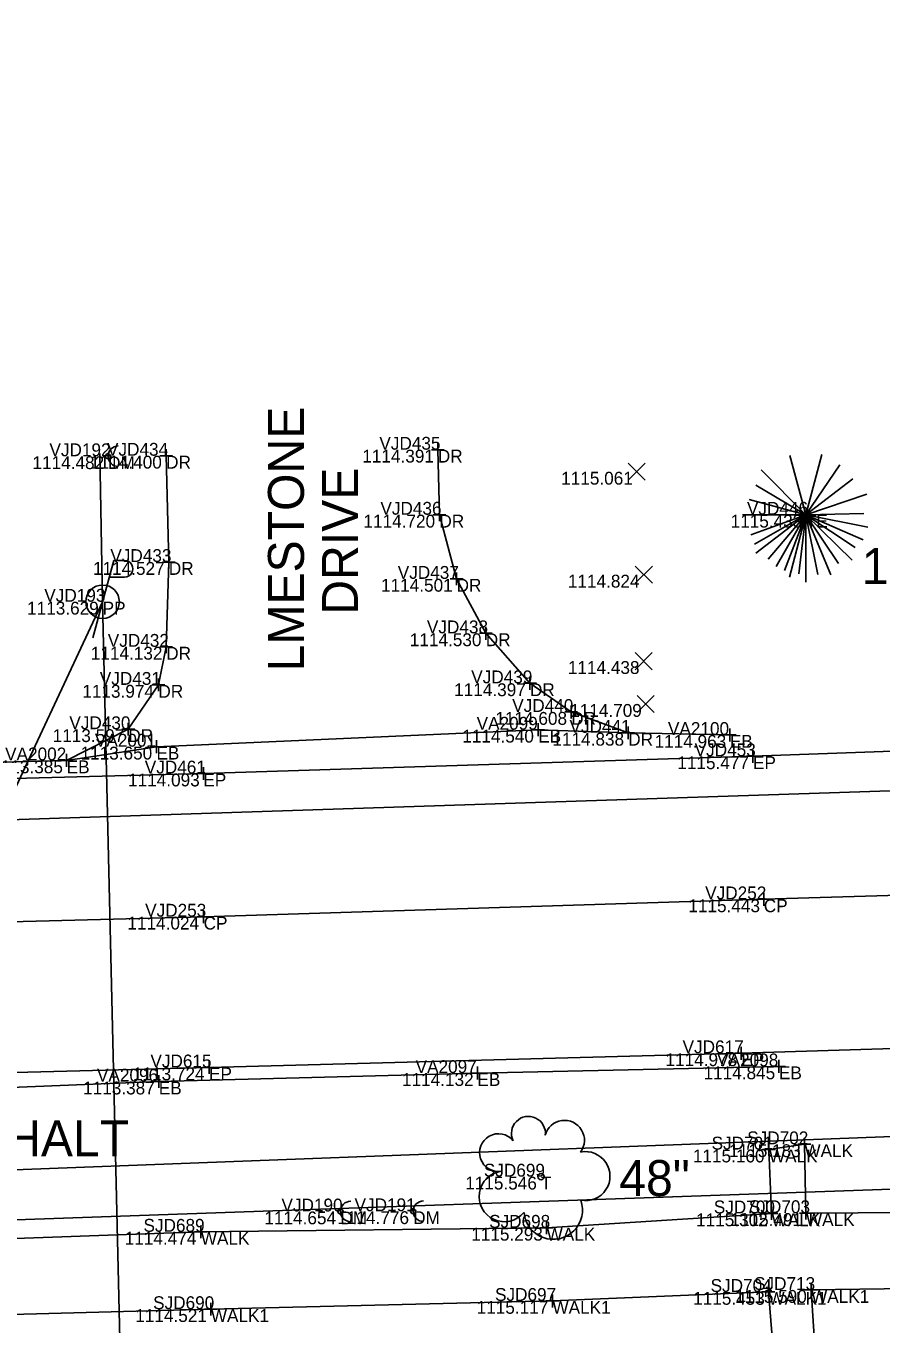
# Model space of a CAD drawing. Extents: x 1629915 to 1630675, y 484401 to 484601.
# Drawn here: x 1630554.5 to 1630621.1, y 484466.8 to 484567.8 of the extents above; entities that cross this region are included whole.
import ezdxf

# ---------------------------------------------------------------- set-up
doc = ezdxf.new("R2010")
doc.units = 0
for name, color, linetype in [('BR_X_Sub_Foot_Object', 7, 'Continuous'), ('PV_X_COP', 7, 'Continuous'), ('PV_X_Driveway', 7, 'Continuous'), ('PV_X_EOP', 7, 'Continuous'), ('PV_X_Shoulder_Aggregate', 7, 'Continuous'), ('PV_X_Walk', 7, 'Continuous'), ('SV_X_Random_Point', 7, 'Continuous'), ('SV_X_Shot_Marker', 7, 'Continuous'), ('SV_X_Text_Comment', 7, 'Continuous'), ('SV_X_Text_Elevation', 7, 'Continuous'), ('SV_X_Text_Name', 7, 'Continuous'), ('TX_X_20', 7, 'Continuous'), ('UT_X_Electric_Cells', 7, 'Continuous'), ('UT_X_Misc_Cells', 7, 'Continuous'), ('UT_X_Sanitary_Line', 7, 'Continuous'), ('UT_X_Water', 7, 'Continuous'), ('VG_X_Cells', 7, 'Continuous')]:
    doc.layers.add(name, color=color, linetype=linetype)

msp = doc.modelspace()

# ---------------------------------------------------------------- linework, layer by layer
at = {"layer": 'BR_X_Sub_Foot_Object'}
for p, q in [((1630560.47, 484522.99), (1630560.26, 484534.52)), ((1630537.67, 484474.32), (1630560.47, 484522.99)), ((1630562.17, 484449.9), (1630560.47, 484522.99)), ((1630537.67, 484474.32), (1630673.62, 484479.09))]:
    msp.add_line(p, q, dxfattribs=at)
at = {"layer": 'PV_X_COP'}
msp.add_lwpolyline([(1630297.37, 484489.97), (1630308.55, 484490.49), (1630361.84, 484492.4), (1630403.57, 484493.66), (1630440.46, 484494.93), (1630486.15, 484496.21), (1630529.23, 484497.46), (1630568.33, 484498.48), (1630611.93, 484499.83), (1630649.71, 484500.97)], dxfattribs=at)
at = {"layer": 'PV_X_Driveway'}
for points in [[(1630557.67, 484510.64), (1630562.47, 484513.07), (1630564.81, 484516.52), (1630565.42, 484519.48), (1630565.62, 484526.08), (1630565.41, 484534.35)], [(1630586.56, 484534.82), (1630586.68, 484529.76), (1630588.02, 484524.77), (1630590.29, 484520.53), (1630593.73, 484516.64), (1630596.94, 484514.41), (1630601.38, 484512.79)]]:
    msp.add_lwpolyline(points, dxfattribs=at)
at = {"layer": 'PV_X_EOP'}
for points in [[(1630649.54, 484512.34), (1630611.09, 484510.96), (1630568.31, 484509.62), (1630527.92, 484508.55), (1630486.05, 484507.69), (1630439.97, 484506.41), (1630403.1, 484505.48), (1630361.88, 484504.43), (1630301.74, 484502.19)], [(1630292.71, 484478.56), (1630303.89, 484478.68), (1630360.91, 484480.85), (1630403.55, 484482.24), (1630442.06, 484483.47), (1630486.34, 484484.8), (1630529.42, 484485.73), (1630568.75, 484486.75), (1630610.18, 484487.85), (1630650.03, 484489.09)]]:
    msp.add_lwpolyline(points, dxfattribs=at)
at = {"layer": 'PV_X_Shoulder_Aggregate'}
for points in [[(1630609.29, 484512.62), (1630601.38, 484512.79), (1630594.37, 484513.03), (1630564.66, 484511.71), (1630557.67, 484510.64), (1630535.06, 484510.05), (1630513.96, 484509.73), (1630489.96, 484510.39), (1630468.46, 484511.02), (1630445.09, 484511.2), (1630420.71, 484511.45), (1630393.49, 484511.94), (1630369.15, 484512.29), (1630344.7, 484511.85), (1630320.66, 484510.61), (1630304.12, 484509.44), (1630303.96, 484508.98)], [(1630290.02, 484472.09), (1630316.06, 484472.69), (1630342.81, 484473.66), (1630368.02, 484474.92), (1630386.58, 484475.76), (1630401.76, 484475.86), (1630425.59, 484476.97), (1630451.8, 484477.68), (1630475.37, 484478.48), (1630505.19, 484479.36), (1630508.15, 484481.33), (1630508.06, 484484.39), (1630516.81, 484484.74), (1630516.95, 484481.1), (1630520.69, 484479.6), (1630540.99, 484479.18), (1630540.51, 484484.67), (1630564.84, 484485.65), (1630589.64, 484486.31), (1630613.11, 484486.83)]]:
    msp.add_lwpolyline(points, dxfattribs=at)
at = {"layer": 'PV_X_Walk'}
for p, q in [((1630615.09, 484480.77), (1630612.33, 484480.36)), ((1630615.21, 484475.41), (1630615.09, 484480.77)), ((1630612.33, 484480.36), (1630612.53, 484475.39)), ((1630612.53, 484475.39), (1630595.02, 484474.27)), ((1630631.16, 484475.53), (1630615.21, 484475.41)), ((1630568.11, 484473.96), (1630535.86, 484472.8)), ((1630595.02, 484474.27), (1630568.11, 484473.96))]:
    msp.add_line(p, q, dxfattribs=at)
msp.add_lwpolyline([(1630493.48, 484465.78), (1630510.56, 484466.34), (1630535.88, 484467.05), (1630568.89, 484467.94), (1630595.48, 484468.58), (1630612.29, 484469.28), (1630612.76, 484463.55), (1630612.78, 484463.44), (1630611.46, 484463.36), (1630611.74, 484459.19), (1630617.57, 484459.66), (1630617.01, 484463.77), (1630616.02, 484463.69), (1630615.97, 484463.78), (1630615.61, 484469.43), (1630634.53, 484469.7), (1630634.52, 484474.41), (1630639.35, 484473.67), (1630639.45, 484470.09), (1630649.39, 484470.38)], dxfattribs=at)
at = {"layer": 'SV_X_Random_Point'}
for p, q in [((1630601.37, 484532.44), (1630602.71, 484533.77)), ((1630601.37, 484533.77), (1630602.71, 484532.44)), ((1630601.93, 484524.43), (1630603.26, 484525.76)), ((1630601.93, 484525.76), (1630603.26, 484524.43)), ((1630601.92, 484517.7), (1630603.25, 484519.04)), ((1630601.92, 484519.04), (1630603.25, 484517.7)), ((1630602.07, 484514.36), (1630603.41, 484515.7)), ((1630602.07, 484515.7), (1630603.41, 484514.36))]:
    msp.add_line(p, q, dxfattribs=at)
at = {"layer": 'SV_X_Shot_Marker'}
for p, q in [((1630586.56, 484535.32), (1630586.56, 484534.32)), ((1630564.91, 484534.35), (1630565.91, 484534.35)), ((1630565.41, 484534.85), (1630565.41, 484533.85)), ((1630565.41, 484534.35), (1630565.41, 484534.35)), ((1630586.06, 484534.82), (1630587.06, 484534.82)), ((1630586.56, 484534.82), (1630586.56, 484534.82)), ((1630586.68, 484530.26), (1630586.68, 484529.26)), ((1630586.18, 484529.76), (1630587.18, 484529.76)), ((1630586.68, 484529.76), (1630586.68, 484529.76)), ((1630565.12, 484526.08), (1630566.12, 484526.08)), ((1630565.62, 484526.58), (1630565.62, 484525.58)), ((1630565.62, 484526.08), (1630565.62, 484526.08)), ((1630588.02, 484525.27), (1630588.02, 484524.27)), ((1630587.52, 484524.77), (1630588.52, 484524.77)), ((1630588.02, 484524.77), (1630588.02, 484524.77)), ((1630590.29, 484521.03), (1630590.29, 484520.03)), ((1630565.42, 484519.98), (1630565.42, 484518.98)), ((1630589.79, 484520.53), (1630590.79, 484520.53)), ((1630590.29, 484520.53), (1630590.29, 484520.53)), ((1630564.92, 484519.48), (1630565.92, 484519.48)), ((1630565.42, 484519.48), (1630565.42, 484519.48)), ((1630564.81, 484517.02), (1630564.81, 484516.02)), ((1630593.73, 484517.14), (1630593.73, 484516.14)), ((1630564.31, 484516.52), (1630565.31, 484516.52)), ((1630564.81, 484516.52), (1630564.81, 484516.52)), ((1630593.23, 484516.64), (1630594.23, 484516.64)), ((1630593.73, 484516.64), (1630593.73, 484516.64)), ((1630596.94, 484514.91), (1630596.94, 484513.91)), ((1630596.44, 484514.41), (1630597.44, 484514.41)), ((1630596.94, 484514.41), (1630596.94, 484514.41)), ((1630561.97, 484513.07), (1630562.97, 484513.07)), ((1630562.47, 484513.57), (1630562.47, 484512.57)), ((1630562.47, 484513.07), (1630562.47, 484513.07)), ((1630593.87, 484513.03), (1630594.87, 484513.03)), ((1630594.37, 484513.53), (1630594.37, 484512.53)), ((1630594.37, 484513.03), (1630594.37, 484513.03)), ((1630600.88, 484512.79), (1630601.88, 484512.79)), ((1630601.38, 484513.29), (1630601.38, 484512.29)), ((1630601.38, 484512.79), (1630601.38, 484512.79)), ((1630609.29, 484513.12), (1630609.29, 484512.12)), ((1630564.16, 484511.71), (1630565.16, 484511.71)), ((1630564.66, 484512.21), (1630564.66, 484511.21)), ((1630564.66, 484511.71), (1630564.66, 484511.71)), ((1630608.79, 484512.62), (1630609.79, 484512.62)), ((1630609.29, 484512.62), (1630609.29, 484512.62)), ((1630557.67, 484511.14), (1630557.67, 484510.14)), ((1630610.59, 484510.96), (1630611.59, 484510.96)), ((1630611.09, 484511.46), (1630611.09, 484510.46)), ((1630611.09, 484510.96), (1630611.09, 484510.96)), ((1630557.17, 484510.64), (1630558.17, 484510.64)), ((1630557.67, 484510.64), (1630557.67, 484510.64)), ((1630568.31, 484510.12), (1630568.31, 484509.12)), ((1630567.81, 484509.62), (1630568.81, 484509.62)), ((1630568.31, 484509.62), (1630568.31, 484509.62)), ((1630611.43, 484499.83), (1630612.43, 484499.83)), ((1630611.93, 484500.33), (1630611.93, 484499.33)), ((1630611.93, 484499.83), (1630611.93, 484499.83)), ((1630568.33, 484498.98), (1630568.33, 484497.98)), ((1630567.83, 484498.48), (1630568.83, 484498.48)), ((1630568.33, 484498.48), (1630568.33, 484498.48)), ((1630609.68, 484487.85), (1630610.68, 484487.85)), ((1630610.18, 484488.35), (1630610.18, 484487.35)), ((1630610.18, 484487.85), (1630610.18, 484487.85)), ((1630568.25, 484486.75), (1630569.25, 484486.75)), ((1630568.75, 484487.25), (1630568.75, 484486.25)), ((1630568.75, 484486.75), (1630568.75, 484486.75)), ((1630589.64, 484486.81), (1630589.64, 484485.81)), ((1630612.61, 484486.83), (1630613.61, 484486.83)), ((1630613.11, 484487.33), (1630613.11, 484486.33)), ((1630613.11, 484486.83), (1630613.11, 484486.83)), ((1630564.34, 484485.65), (1630565.34, 484485.65)), ((1630564.84, 484486.15), (1630564.84, 484485.15)), ((1630564.84, 484485.65), (1630564.84, 484485.65)), ((1630589.14, 484486.31), (1630590.14, 484486.31)), ((1630589.64, 484486.31), (1630589.64, 484486.31)), ((1630612.33, 484480.86), (1630612.33, 484479.86)), ((1630614.59, 484480.77), (1630615.59, 484480.77)), ((1630615.09, 484481.27), (1630615.09, 484480.27)), ((1630615.09, 484480.77), (1630615.09, 484480.77)), ((1630611.83, 484480.36), (1630612.83, 484480.36)), ((1630612.33, 484480.36), (1630612.33, 484480.36)), ((1630612.03, 484475.39), (1630613.03, 484475.39)), ((1630612.53, 484475.89), (1630612.53, 484474.89)), ((1630612.53, 484475.39), (1630612.53, 484475.39)), ((1630614.71, 484475.41), (1630615.71, 484475.41)), ((1630615.21, 484475.91), (1630615.21, 484474.91)), ((1630615.21, 484475.41), (1630615.21, 484475.41)), ((1630568.11, 484474.46), (1630568.11, 484473.46)), ((1630595.02, 484474.77), (1630595.02, 484473.77)), ((1630567.61, 484473.96), (1630568.61, 484473.96)), ((1630568.11, 484473.96), (1630568.11, 484473.96)), ((1630594.52, 484474.27), (1630595.52, 484474.27)), ((1630595.02, 484474.27), (1630595.02, 484474.27)), ((1630612.29, 484469.78), (1630612.29, 484468.78)), ((1630615.11, 484469.43), (1630616.11, 484469.43)), ((1630615.61, 484469.93), (1630615.61, 484468.93)), ((1630615.61, 484469.43), (1630615.61, 484469.43)), ((1630568.89, 484468.44), (1630568.89, 484467.44)), ((1630594.98, 484468.58), (1630595.98, 484468.58)), ((1630595.48, 484469.08), (1630595.48, 484468.08)), ((1630595.48, 484468.58), (1630595.48, 484468.58)), ((1630611.79, 484469.28), (1630612.79, 484469.28)), ((1630612.29, 484469.28), (1630612.29, 484469.28)), ((1630568.39, 484467.94), (1630569.39, 484467.94)), ((1630568.89, 484467.94), (1630568.89, 484467.94))]:
    msp.add_line(p, q, dxfattribs=at)
at = {"layer": 'UT_X_Electric_Cells'}
for p, q in [((1630561.33, 484526.19), (1630559.72, 484520.19)), ((1630561.33, 484526.19), (1630562.18, 484526.19)), ((1630560.99, 484524.91), (1630562.18, 484524.91))]:
    msp.add_line(p, q, dxfattribs=at)
msp.add_circle((1630560.47, 484522.99), 1.3, dxfattribs=at)
msp.add_arc((1630562.19, 484525.55), 0.638, 268.8767, 91.1233, dxfattribs=at)
at = {"layer": 'UT_X_Misc_Cells'}
for centre in [(1630560.89, 484534.31), (1630578.98, 484475.54), (1630584.64, 484475.56)]:
    msp.add_circle(centre, 0.2, dxfattribs=at)
for centre in [(1630561.69, 484534.31), (1630585.44, 484475.56), (1630579.78, 484475.54)]:
    msp.add_arc(centre, 0.8, 90, 270, dxfattribs=at)
at = {"layer": 'UT_X_Sanitary_Line'}
msp.add_lwpolyline([(1629930.75, 484483.73), (1630048.13, 484488.31), (1630252.72, 484494.6), (1630261.76, 484567.79), (1630373.42, 484500.09), (1630654.86, 484509.35)], dxfattribs=at)
at = {"layer": 'UT_X_Water'}
msp.add_line((1630348.22, 484470.93), (1630675.08, 484483.41), dxfattribs=at)
at = {"layer": 'VG_X_Cells'}
for p, q in [((1630615.21, 484529.76), (1630613.97, 484534.37)), ((1630615.21, 484529.76), (1630616.46, 484534.45)), ((1630615.21, 484529.76), (1630611.72, 484533.24)), ((1630615.21, 484529.76), (1630617.86, 484533.64)), ((1630615.21, 484529.76), (1630611.3, 484532.05)), ((1630615.21, 484529.76), (1630618.86, 484532.56)), ((1630615.21, 484529.76), (1630610.79, 484530.94)), ((1630615.21, 484529.76), (1630619.94, 484531.36)), ((1630610.27, 484529.76), (1630615.21, 484529.76)), ((1630615.21, 484529.76), (1630610.92, 484528.19)), ((1630615.21, 484529.76), (1630611.22, 484527.47)), ((1630615.21, 484529.76), (1630611.3, 484526.76)), ((1630615.21, 484529.76), (1630612.26, 484526.29)), ((1630615.21, 484529.76), (1630612.89, 484525.74)), ((1630615.21, 484529.76), (1630613.54, 484525.42)), ((1630615.21, 484529.76), (1630613.94, 484524.9)), ((1630615.21, 484529.76), (1630614.67, 484525.16)), ((1630615.21, 484529.76), (1630619.72, 484529.85)), ((1630615.21, 484524.52), (1630615.21, 484529.76)), ((1630615.21, 484529.76), (1630616.13, 484525.12)), ((1630615.21, 484529.76), (1630617.14, 484525.09)), ((1630615.21, 484529.76), (1630617.74, 484525.96)), ((1630615.21, 484529.76), (1630618.8, 484526.23)), ((1630615.21, 484529.76), (1630619.03, 484527.2)), ((1630615.21, 484529.76), (1630619.67, 484527.81)), ((1630615.21, 484529.76), (1630620.04, 484528.8))]:
    msp.add_line(p, q, dxfattribs=at)
msp.add_circle((1630594.59, 484478.25), 0.24, dxfattribs=at)
for centre, radius, start, end in [((1630593.61, 484481.62), 1.32, 354.0047, 205.9741), ((1630596.42, 484481.08), 1.55, 323.83, 165.0376), ((1630591.28, 484480.12), 1.47, 39.0625, 279.5412), ((1630598.05, 484478.29), 1.91, 259.1453, 101.4596), ((1630591.74, 484476.71), 1.97, 96.1722, 320.5737), ((1630595.54, 484475.65), 2.28, 184.9476, 19.4572)]:
    msp.add_arc(centre, radius, start, end, dxfattribs=at)

# ---------------------------------------------------------------- texts
at = {"layer": 'SV_X_Text_Comment'}
for s, p in [('DM', (1630560.89, 484533.31)), ('DR', (1630565.41, 484533.35)), ('DR', (1630586.56, 484533.82)), ('DR', (1630586.68, 484528.76)), ('TE', (1630615.21, 484528.76)), ('DR', (1630565.62, 484525.08)), ('DR', (1630588.02, 484523.77)), ('PP', (1630560.47, 484521.99)), ('DR', (1630590.29, 484519.53)), ('DR', (1630565.42, 484518.48)), ('DR', (1630564.81, 484515.52)), ('DR', (1630593.73, 484515.64)), ('DR', (1630596.94, 484513.41)), ('DR', (1630562.47, 484512.07)), ('EB', (1630594.37, 484512.03)), ('DR', (1630601.38, 484511.79)), ('EB', (1630564.66, 484510.71)), ('EB', (1630609.29, 484511.62)), ('EP', (1630611.09, 484509.96)), ('EB', (1630557.67, 484509.64)), ('EP', (1630568.31, 484508.62)), ('CP', (1630611.93, 484498.83)), ('CP', (1630568.33, 484497.48)), ('EP', (1630610.18, 484486.85)), ('EP', (1630568.75, 484485.75)), ('EB', (1630613.11, 484485.83)), ('EB', (1630564.84, 484484.65)), ('EB', (1630589.64, 484485.31)), ('WALK', (1630615.09, 484479.77)), ('WALK', (1630612.33, 484479.36)), ('T', (1630594.59, 484477.25)), ('DM', (1630578.98, 484474.54)), ('DM', (1630584.64, 484474.56)), ('WALK', (1630612.53, 484474.39)), ('WALK', (1630615.21, 484474.41)), ('WALK', (1630568.11, 484472.96)), ('WALK', (1630595.02, 484473.27)), ('WALK1', (1630615.61, 484468.43)), ('WALK1', (1630595.48, 484467.58)), ('WALK1', (1630612.29, 484468.28)), ('WALK1', (1630568.89, 484466.94))]:
    msp.add_text(s, height=1, dxfattribs=at).set_placement(p)
at = {"layer": 'SV_X_Text_Elevation'}
for s, p in [('1114.482', (1630555.01, 484533.31)), ('1114.400', (1630559.5, 484533.35)), ('1114.391', (1630580.68, 484533.82)), ('1115.061', (1630596.16, 484532.1)), ('1114.720', (1630580.77, 484528.76)), ('1115.433', (1630609.35, 484528.76)), ('1114.527', (1630559.72, 484525.08)), ('1114.824', (1630596.68, 484524.09)), ('1114.501', (1630582.14, 484523.77)), ('1113.629', (1630554.59, 484521.99)), ('1114.530', (1630584.38, 484519.53)), ('1114.132', (1630559.55, 484518.48)), ('1114.438', (1630596.68, 484517.37)), ('1113.974', (1630558.89, 484515.52)), ('1114.397', (1630587.83, 484515.64)), ('1114.709', (1630596.86, 484514.03)), ('1114.608', (1630591.04, 484513.41)), ('1113.597', (1630556.58, 484512.07)), ('1114.540', (1630588.46, 484512.03)), ('1114.838', (1630595.48, 484511.79)), ('1113.650', (1630558.75, 484510.71)), ('1114.963', (1630603.43, 484511.62)), ('1115.477', (1630605.2, 484509.96)), ('1113.385', (1630551.8, 484509.64)), ('1114.093', (1630562.45, 484508.62)), ('1115.443', (1630606.06, 484498.83)), ('1114.024', (1630562.4, 484497.48)), ('1114.978', (1630604.28, 484486.85)), ('1113.724', (1630562.83, 484485.75)), ('1114.845', (1630607.24, 484485.83)), ('1113.387', (1630558.95, 484484.65)), ('1114.132', (1630583.77, 484485.31)), ('1115.183', (1630609.23, 484479.77)), ('1115.160', (1630606.41, 484479.36)), ('1115.546', (1630588.69, 484477.25)), ('1114.654', (1630573.06, 484474.54)), ('1114.776', (1630578.74, 484474.56)), ('1115.302', (1630606.66, 484474.39)), ('1115.491', (1630609.33, 484474.41)), ('1114.474', (1630562.19, 484472.96)), ('1115.293', (1630589.16, 484473.27)), ('1115.453', (1630606.43, 484468.28)), ('1115.590', (1630609.7, 484468.43)), ('1115.117', (1630589.58, 484467.58)), ('1114.521', (1630563.01, 484466.94))]:
    msp.add_text(s, height=1, dxfattribs=at).set_placement(p)
at = {"layer": 'SV_X_Text_Name'}
for s, p in [('VJD192', (1630556.33, 484534.31)), ('VJD434', (1630560.81, 484534.35)), ('VJD435', (1630582.01, 484534.82)), ('VJD436', (1630582.09, 484529.76)), ('VJD446', (1630610.62, 484529.76)), ('VJD433', (1630561.07, 484526.08)), ('VJD437', (1630583.44, 484524.77)), ('VJD193', (1630555.93, 484522.99)), ('VJD438', (1630585.71, 484520.53)), ('VJD432', (1630560.87, 484519.48)), ('VJD431', (1630560.25, 484516.52)), ('VJD439', (1630589.16, 484516.64)), ('VJD440', (1630592.35, 484514.41)), ('VJD430', (1630557.88, 484513.07)), ('VA2099', (1630589.58, 484513.03)), ('VJD441', (1630596.81, 484512.79)), ('VA2001', (1630559.87, 484511.71)), ('VA2100', (1630604.47, 484512.62)), ('VJD453', (1630606.55, 484510.96)), ('VA2002', (1630552.88, 484510.64)), ('VJD461', (1630563.75, 484509.62)), ('VJD252', (1630607.37, 484499.83)), ('VJD253', (1630563.78, 484498.48)), ('VJD617', (1630605.61, 484487.85)), ('VJD615', (1630564.19, 484486.75)), ('VA2098', (1630608.3, 484486.83)), ('VA2096', (1630560.03, 484485.65)), ('VA2097', (1630584.83, 484486.31)), ('SJD702', (1630610.64, 484480.77)), ('SJD701', (1630607.87, 484480.36)), ('SJD699', (1630590.14, 484478.25)), ('VJD190', (1630574.39, 484475.54)), ('VJD191', (1630580.08, 484475.56)), ('SJD700', (1630608.04, 484475.39)), ('SJD703', (1630610.77, 484475.41)), ('SJD689', (1630563.65, 484473.96)), ('SJD698', (1630590.55, 484474.27)), ('SJD713', (1630611.17, 484469.43)), ('SJD697', (1630591.01, 484468.58)), ('SJD704', (1630607.79, 484469.28)), ('SJD690', (1630564.4, 484467.94))]:
    msp.add_text(s, height=1, dxfattribs=at).set_placement(p)
at = {"layer": 'TX_X_20'}
for s, rotation, p in [('LMESTONE', 90, (1630576.14, 484517.57)), ('DRIVE', 90, (1630580.34, 484521.98)), ('ASPHALT', 360, (1630545.47, 484479.82))]:
    msp.add_text(s, height=2.8, rotation=rotation, dxfattribs=at).set_placement(p)
for s, p in [('12"', (1630619.56, 484524.36)), ('48"', (1630600.68, 484476.74))]:
    msp.add_text(s, height=2.8, dxfattribs=at).set_placement(p)

doc.saveas('drawing.dxf')
